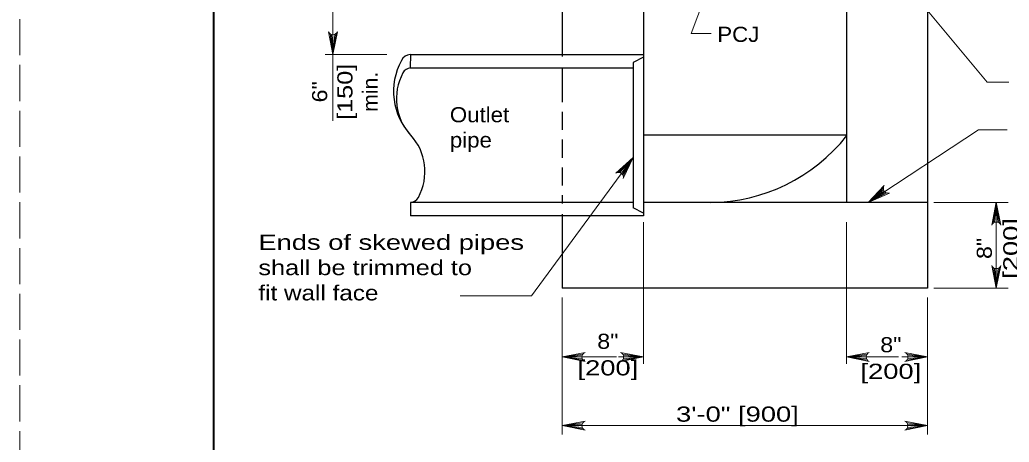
# Model space of a CAD drawing. Extents: x 339.1 to 373.1, y 1412.7 to 1456.7.
# Drawn here: x 339.06 to 349.27, y 1423.77 to 1428.13 of the extents above; entities that cross this region are included whole.
import ezdxf
from ezdxf.enums import TextEntityAlignment as Align

# ---------------------------------------------------------------- set-up
doc = ezdxf.new("R2010")
doc.units = 0
doc.header["$LTSCALE"] = 0.062
doc.linetypes.add('LONG_DASHED', pattern=[7.5, 6, -1.5])
doc.linetypes.add('MEDIUM_DASHED', pattern=[4.5, 3, -1.5])
doc.layers.add('1', color=7, linetype='Continuous', lineweight=13)

msp = doc.modelspace()

# ---------------------------------------------------------------- linework, layer by layer
at = {"layer": '1', "lineweight": 25}
for p, q in [((345.49225, 1430.72742), (345.49225, 1426.24892)), ((348.424, 1430.06225), (348.424, 1425.36217)), ((343.09025, 1427.77333), (343.0885, 1427.63458)), ((343.09025, 1427.77333), (345.49225, 1427.77333)), ((345.49225, 1427.74558), (345.38758, 1427.69017)), ((345.38758, 1427.69017), (345.38758, 1426.1935)), ((343.0885, 1427.63458), (345.38758, 1427.63458)), ((347.58642, 1426.94192), (345.49225, 1426.94192)), ((345.49225, 1426.24892), (345.49225, 1426.11042)), ((348.424, 1426.24892), (345.49458, 1426.24892)), ((345.49225, 1426.13808), (345.38758, 1426.1935)), ((345.49225, 1426.11042), (343.09192, 1426.11042)), ((344.65467, 1426.11042), (344.65467, 1425.36217)), ((348.424, 1425.36217), (344.65467, 1425.36217))]:
    msp.add_line(p, q, dxfattribs=at)
at = {"layer": '1'}
for p, q in [((342.29, 1428.43842), (342.29, 1427.08917)), ((346.15242, 1428.43842), (345.98342, 1427.99108)), ((342.26017, 1427.98658), (342.29, 1427.77333)), ((342.27492, 1427.97933), (342.29, 1427.77333)), ((342.323, 1427.98908), (342.29, 1427.77333)), ((342.30917, 1427.98092), (342.29, 1427.77333)), ((342.29, 1427.97717), (342.29, 1427.77333)), ((345.98342, 1427.99108), (346.19117, 1427.99108)), ((342.84517, 1427.77333), (342.21133, 1427.77333)), ((345.38758, 1426.71133), (344.33833, 1425.28383)), ((345.23233, 1426.55792), (345.38758, 1426.71133)), ((345.24825, 1426.55625), (345.38758, 1426.71133)), ((345.26592, 1426.54783), (345.38758, 1426.71133)), ((345.27667, 1426.53708), (345.38758, 1426.71133)), ((345.28417, 1426.52242), (345.38758, 1426.71133)), ((347.96692, 1426.39517), (347.80975, 1426.24792)), ((347.9695, 1426.37892), (347.80975, 1426.24792)), ((347.97642, 1426.36533), (347.80975, 1426.24792)), ((347.9905, 1426.35183), (347.80975, 1426.24792)), ((348.00517, 1426.34525), (347.80975, 1426.24792)), ((348.48917, 1426.24892), (349.25442, 1426.24892)), ((349.09908, 1426.0335), (349.132, 1426.24925)), ((349.11283, 1426.04167), (349.132, 1426.24925)), ((349.132, 1425.99883), (349.132, 1426.24925)), ((349.132, 1426.04542), (349.132, 1426.24925)), ((349.14708, 1426.04325), (349.132, 1426.24925)), ((349.16183, 1426.036), (349.132, 1426.24925)), ((345.49225, 1426.044), (345.49225, 1424.58242)), ((349.132, 1425.36217), (349.132, 1426.07892)), ((349.10217, 1425.57542), (349.132, 1425.36217)), ((349.11692, 1425.56817), (349.132, 1425.36217)), ((349.165, 1425.57792), (349.132, 1425.36217)), ((349.15117, 1425.56975), (349.132, 1425.36217)), ((349.132, 1425.566), (349.132, 1425.36217)), ((348.48917, 1425.36217), (349.25442, 1425.36217)), ((343.60325, 1425.28383), (344.33833, 1425.28383)), ((344.65467, 1425.26683), (344.65467, 1423.85575)), ((348.424, 1425.26683), (348.424, 1425.0025)), ((348.424, 1425.0025), (348.424, 1423.85575)), ((344.86792, 1424.684), (344.65467, 1424.65417)), ((344.86067, 1424.66925), (344.65467, 1424.65417)), ((344.65467, 1424.65417), (345.215, 1424.65417)), ((344.8585, 1424.65417), (344.65467, 1424.65417)), ((344.86225, 1424.635), (344.65467, 1424.65417)), ((344.87042, 1424.62117), (344.65467, 1424.65417)), ((345.23683, 1424.65417), (345.49225, 1424.65417)), ((345.2765, 1424.62117), (345.49225, 1424.65417)), ((345.279, 1424.684), (345.49225, 1424.65417)), ((345.28467, 1424.635), (345.49225, 1424.65417)), ((345.28625, 1424.66925), (345.49225, 1424.65417)), ((345.28842, 1424.65417), (345.49225, 1424.65417)), ((347.79967, 1424.684), (347.58642, 1424.65417)), ((347.79242, 1424.66925), (347.58642, 1424.65417)), ((347.58642, 1424.65417), (348.12475, 1424.65417)), ((347.79025, 1424.65417), (347.58642, 1424.65417)), ((347.794, 1424.635), (347.58642, 1424.65417)), ((347.80217, 1424.62117), (347.58642, 1424.65417)), ((348.15617, 1424.65417), (348.424, 1424.65417)), ((348.20825, 1424.62117), (348.424, 1424.65417)), ((348.21075, 1424.684), (348.424, 1424.65417)), ((348.21642, 1424.635), (348.424, 1424.65417)), ((348.218, 1424.66925), (348.424, 1424.65417)), ((348.22017, 1424.65417), (348.424, 1424.65417)), ((344.86792, 1423.976), (344.65467, 1423.94617)), ((348.21067, 1423.976), (348.42392, 1423.94617)), ((344.86067, 1423.96117), (344.65467, 1423.94617)), ((344.8585, 1423.94617), (344.65467, 1423.94617)), ((344.86225, 1423.927), (344.65467, 1423.94617)), ((344.87042, 1423.91317), (344.65467, 1423.94617)), ((348.20817, 1423.91317), (348.42392, 1423.94617)), ((348.21633, 1423.927), (348.42392, 1423.94617)), ((348.21783, 1423.96117), (348.42392, 1423.94617)), ((348.22008, 1423.94617), (348.42392, 1423.94617))]:
    msp.add_line(p, q, dxfattribs=at)
at = {"layer": '1', "linetype": 'MEDIUM_DASHED', "lineweight": 25}
for p, q in [((344.65467, 1427.77333), (344.65467, 1427.75458)), ((344.65467, 1427.62983), (344.65467, 1427.46758)), ((344.65467, 1427.46758), (344.65467, 1426.2365)), ((344.65467, 1426.12808), (344.65467, 1426.11042))]:
    msp.add_line(p, q, dxfattribs=at)
at = {"layer": '1', "linetype": 'LONG_DASHED'}
msp.add_lwpolyline([(339.0605, 1412.7455), (373.0605, 1412.7455), (373.0605, 1434.7455), (339.0605, 1434.7455)], close=True, dxfattribs=at)
at = {"layer": '1', "lineweight": 25}
for points in [[(372.5605, 1413.2455), (341.0605, 1413.2455), (341.0605, 1434.2455)], [(344.65467, 1430.23983), (344.65467, 1428.43842), (344.65467, 1427.77333)], [(347.58642, 1429.66925), (347.58642, 1428.85175), (347.58642, 1426.24892)], [(345.38758, 1426.24892), (343.09192, 1426.24892), (343.09192, 1426.11042)]]:
    msp.add_lwpolyline(points, dxfattribs=at)
at = {"layer": '1', "lineweight": 40}
msp.add_lwpolyline([(341.0605, 1434.2455), (372.5605, 1434.2455), (372.5605, 1413.2455), (341.0605, 1413.2455)], close=True, dxfattribs=at)
at = {"layer": '1'}
for points in [[(348.00525, 1428.73017), (349.03675, 1427.48925), (349.26192, 1427.48925)], [(342.33708, 1428.00892), (342.29, 1427.77333), (342.24283, 1428.00892)], [(347.80975, 1426.24792), (348.94692, 1426.9955), (349.24267, 1426.9955)], [(345.20917, 1426.5505), (345.38758, 1426.71133), (345.28475, 1426.49425)], [(348.0295, 1426.34508), (347.80975, 1426.24792), (347.97517, 1426.42217)], [(349.08492, 1426.01367), (349.132, 1426.24925), (349.17917, 1426.01367)], [(347.58642, 1426.044), (347.58642, 1424.97533), (347.58642, 1424.58242)], [(349.17917, 1425.59775), (349.132, 1425.36217), (349.08492, 1425.59775)], [(344.89025, 1424.607), (344.65467, 1424.65417), (344.89025, 1424.70125)], [(345.25667, 1424.607), (345.49225, 1424.65417), (345.25667, 1424.70125)], [(347.822, 1424.607), (347.58642, 1424.65417), (347.822, 1424.70125)], [(348.18842, 1424.607), (348.424, 1424.65417), (348.18842, 1424.70125)], [(344.89025, 1423.899), (344.65467, 1423.94617), (344.89025, 1423.99325)], [(348.18833, 1423.899), (348.42392, 1423.94617), (348.18833, 1423.99325)], [(344.65467, 1423.94617), (346.89792, 1423.94617), (348.42392, 1423.94617)]]:
    msp.add_lwpolyline(points, dxfattribs=at)
for centre, start, end in [((342.28993, 1428.0279), 202.08782, 337.91395), ((345.23564, 1426.50706), 345.43854, 121.26467), ((348.01784, 1426.39463), 147.27019, 283.09631), ((349.13208, 1425.99467), 22.08782, 157.91395), ((349.13198, 1425.61675), 202.08782, 337.91395), ((344.90925, 1424.65418), 112.08782, 247.91395), ((345.23767, 1424.65418), 292.08605, 67.91218), ((347.841, 1424.65418), 112.08782, 247.91395), ((348.16942, 1424.65418), 292.08605, 67.91218), ((344.90925, 1423.94618), 112.08782, 247.91395), ((348.16931, 1423.94618), 292.08605, 67.91218)]:
    msp.add_arc(centre, 0.05085, start, end, dxfattribs=at)
at = {"layer": '1', "lineweight": 25}
for centre, major_axis, ratio, start_param, end_param in [((343.09194, 1427.65335), (0, 0.11994), 0.913574, 0.0491937, 1.06207483), ((343.51788, 1427.39284), (0, -0.63774), 0.944544, 4.1886883, 5.49778714), ((343.44669, 1427.31757), (0, -0.53143), 0.944544, 4.1886883, 5.49778714), ((343.09175, 1427.53465), (0, 0.09995), 0.913574, 0.01986786, 1.06207479), ((342.7372, 1426.56622), (0, 0.53143), 0.944544, 4.1886883, 5.49778714), ((346.18373, 1428.20804), (0, -1.95913), 0.944544, 0.00267506, 0.86456926), ((343.09213, 1426.34914), (0, -0.09995), 0.913574, 6.28162348, 7.34526009)]:
    msp.add_ellipse(centre, major_axis=major_axis, ratio=ratio, start_param=start_param, end_param=end_param, dxfattribs=at)

# ---------------------------------------------------------------- texts
at = {"layer": '1'}
for s, width, p in [('PCJ', 1.1, (346.47129, 1427.90375)), ('8"', 1.15, (345.12562, 1424.73783)), ('8"', 1.15, (348.04437, 1424.70233)), ('[200]', 1.35, (345.12571, 1424.46383)), ('[200]', 1.35, (348.04446, 1424.42833))]:
    msp.add_text(s, height=0.156, dxfattribs=dict(at, width=width)).set_placement(p, align=Align.CENTER)
for s, width, p in [('[150]', 1.25, (342.49167, 1427.38879)), ('min.', 1.05, (342.75233, 1427.38887)), ('6"', 1.15, (342.231, 1427.38879)), ('[200]', 1.35, (349.36025, 1425.77354)), ('8"', 1.15, (349.08625, 1425.77346))]:
    msp.add_text(s, height=0.156, rotation=90, dxfattribs=dict(at, width=width)).set_placement(p, align=Align.CENTER)
for s, width, p in [('Outlet', 1.1, (343.49608, 1427.07475)), ('pipe', 1.1, (343.49608, 1426.81408)), ('Ends of skewed pipes', 1.35, (341.52133, 1425.75858)), ('shall be trimmed to', 1.25, (341.52133, 1425.49792)), ('fit wall face', 1.2, (341.52133, 1425.23725)), ('3\'-0" [900]', 1.35, (345.8295, 1423.9865))]:
    msp.add_text(s, height=0.156, dxfattribs=dict(at, width=width)).set_placement(p)

doc.saveas('drawing.dxf')
